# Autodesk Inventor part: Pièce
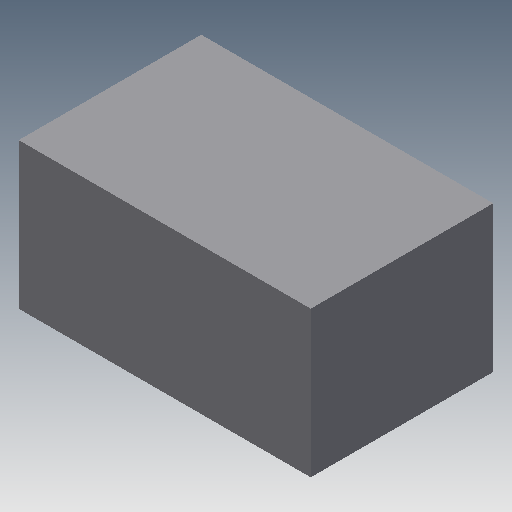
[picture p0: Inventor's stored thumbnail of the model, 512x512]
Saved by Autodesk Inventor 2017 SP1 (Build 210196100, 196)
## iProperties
Shininess: 64.0
Length Units: 11269
Angle Units: 11279
Time Units: 11290
Mass Units: 11283
Length Display Precision: 3
Angle Display Precision: 2
Compacted: True
Part Number: Pièce
Document SubType Name: Modeling
Created: 2003-07
Material: Générique
Designer: trameau
Density: 1 g/cm^3
Appearance: Par défaut
Density: 0.0
Volumn: 0.0
Area: 0.0
PropertySet Name: Model Information
Control State: 0
Master: False
Checked Out: False
Author: trameau
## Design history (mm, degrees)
sketch "Esquisse1"
  geometry: L1 (-12.515, 12.37)-(67.485, 12.37); L2 (67.485, 12.37)-(67.485, -27.63); L3 (67.485, -27.63)-(-12.515, -27.63); L4 (-12.515, -27.63)-(-12.515, 12.37)
  constraints: 8 end point, 2 parallel, 1 horizontal, 1 perpendicular
  dimensions: "d0" = 80 distance between parallel lines of L2 L4; "d1" = 40 distance between parallel lines of L1 L3
extrude "Extrusion1" new body sketch "Esquisse1" distance "d2" = 50; taper "d3" = 0 deg
node "Solide1"
node "Corps solides"
node "Corps surfaciques"
